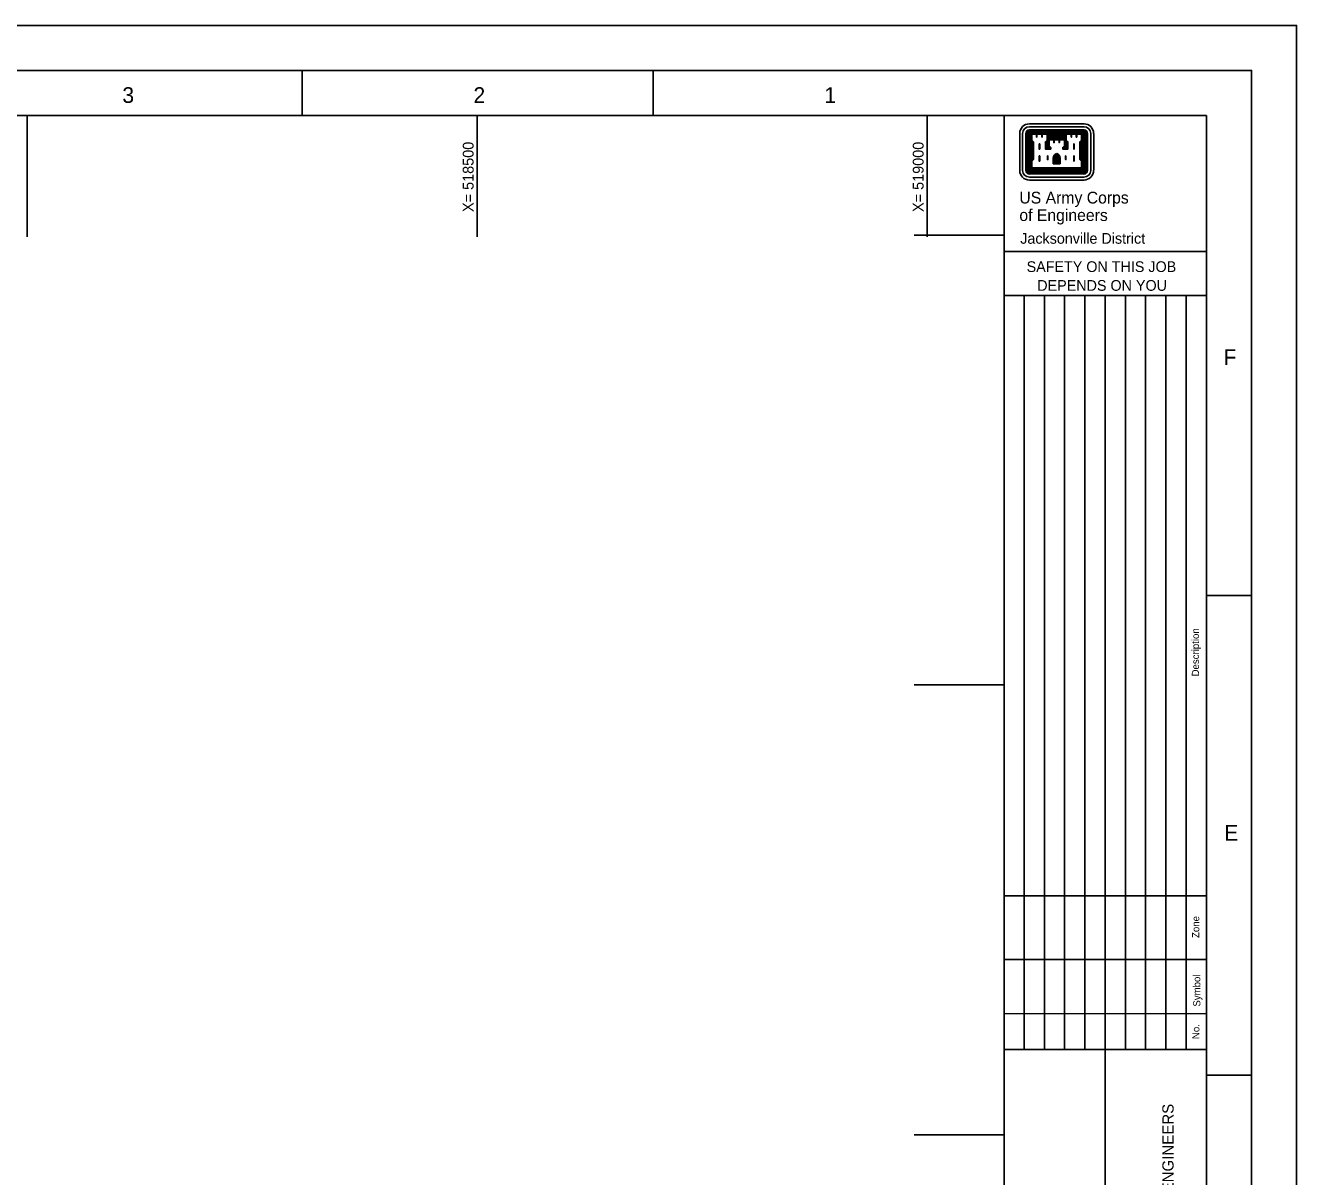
# Model space of a CAD drawing. Extents: x 515010 to 519411, y 1296833 to 1300233.
# Drawn here: x 517998 to 519410, y 1298953 to 1300233 of the extents above; entities that cross this region are included whole.
import ezdxf

# ---------------------------------------------------------------- set-up
doc = ezdxf.new("R2010")
doc.units = 0
for name, color, linetype in [('G-ANNO-NPLT', 7, 'Continuous'), ('G-ANNO-TEXT-LOGO', 7, 'Continuous'), ('G-ANNO-TEXT-TTLB', 7, 'Continuous'), ('G-ANNO-TTLB', 7, 'Continuous'), ('V-TOPO-COOR-STAT', 7, 'Continuous')]:
    doc.layers.add(name, color=color, linetype=linetype)

msp = doc.modelspace()

# ---------------------------------------------------------------- linework, layer by layer
at = {"layer": 'G-ANNO-NPLT'}
msp.add_lwpolyline([(515010.4, 1300233), (519410.4, 1300233), (519410.4, 1296833), (515010.4, 1296833)], close=True, dxfattribs=at)
msp.add_lwpolyline([(519410.4, 1300183), (519410.4, 1300233), (519360.4, 1300233)], dxfattribs=at)
at = {"layer": 'G-ANNO-TEXT-LOGO'}
for p, q in [((519102.8, 1300112.9), (519102.8, 1300071.9)), ((519106, 1300071.9), (519106, 1300112.9)), ((519109.5, 1300112.9), (519109.5, 1300071.9)), ((519110.4, 1300112.9), (519110.4, 1300071.9)), ((519111.2, 1300112.9), (519111.2, 1300071.9)), ((519112.1, 1300112.9), (519112.1, 1300071.9)), ((519113, 1300112.9), (519113, 1300071.9)), ((519174.3, 1300123.6), (519113.5, 1300123.6)), ((519113.5, 1300120.4), (519174.3, 1300120.4)), ((519174.3, 1300117), (519113.5, 1300117)), ((519174.3, 1300116.1), (519113.5, 1300116.1)), ((519174.3, 1300115.2), (519113.5, 1300115.2)), ((519174.3, 1300114.4), (519113.5, 1300114.4)), ((519174.3, 1300113.5), (519113.5, 1300113.5)), ((519113.9, 1300112.9), (519113.9, 1300072.2)), ((519114.7, 1300112.9), (519114.7, 1300073.1)), ((519134.6, 1300112.7), (519153.2, 1300112.7)), ((519134.6, 1300111.8), (519153.2, 1300111.8)), ((519173.1, 1300112.9), (519173.1, 1300073.1)), ((519173.9, 1300112.9), (519173.9, 1300072.2)), ((519174.8, 1300112.9), (519174.8, 1300071.9)), ((519175.7, 1300112.9), (519175.7, 1300071.9)), ((519176.5, 1300112.9), (519176.5, 1300071.9)), ((519177.4, 1300112.9), (519177.4, 1300071.9)), ((519178.3, 1300112.9), (519178.3, 1300071.9)), ((519181.7, 1300112.9), (519181.7, 1300071.9)), ((519185, 1300071.9), (519185, 1300112.9)), ((519115.4, 1300104.2), (519115.4, 1300083.2)), ((519116.3, 1300103.3), (519116.3, 1300084.2)), ((519134.6, 1300111), (519153.2, 1300111)), ((519134.6, 1300110.1), (519153.2, 1300110.1)), ((519134.6, 1300109.2), (519153.2, 1300109.2)), ((519134.6, 1300108.4), (519153.2, 1300108.4)), ((519134.6, 1300107.5), (519153.2, 1300107.5)), ((519171.5, 1300103.3), (519171.5, 1300084.2)), ((519172.4, 1300104.1), (519172.4, 1300083.3)), ((519139.9, 1300079), (519139.9, 1300085.7)), ((519140.7, 1300079), (519140.7, 1300085.7)), ((519141.6, 1300079), (519141.6, 1300085.7)), ((519142.5, 1300079), (519142.5, 1300085.7)), ((519143.3, 1300079), (519143.3, 1300085.7)), ((519144.5, 1300079), (519144.5, 1300085.7)), ((519145.3, 1300079), (519145.3, 1300085.7)), ((519146.2, 1300079), (519146.2, 1300085.7)), ((519147.1, 1300079), (519147.1, 1300085.7)), ((519147.9, 1300079), (519147.9, 1300085.7)), ((519174.3, 1300071.3), (519113.5, 1300071.3)), ((519174.3, 1300070.5), (519113.5, 1300070.5)), ((519174.3, 1300069.6), (519113.5, 1300069.6)), ((519173.9, 1300072.2), (519113.9, 1300072.2)), ((519173.1, 1300073.1), (519114.7, 1300073.1)), ((519139.9, 1300079), (519147.9, 1300079)), ((519174.3, 1300068.7), (519113.5, 1300068.7)), ((519174.3, 1300067.9), (519113.5, 1300067.9)), ((519174.3, 1300064.4), (519113.5, 1300064.4)), ((519113.5, 1300061.1), (519174.3, 1300061.1))]:
    msp.add_line(p, q, dxfattribs=at)
for points in [[(519115.4, 1300112.9), (519115.4, 1300105), (519117.1, 1300103.3), (519117.1, 1300084.2), (519115.4, 1300082.4), (519115.4, 1300073.7), (519172.4, 1300073.7), (519172.4, 1300082.4), (519170.6, 1300084.2), (519170.6, 1300103.3), (519172.4, 1300105), (519172.4, 1300112.9), (519164.9, 1300112.9), (519159.1, 1300112.9), (519153.7, 1300112.9), (519153.7, 1300105), (519155.6, 1300103.3), (519155.6, 1300096.3), (519151.4, 1300096.3), (519151.4, 1300097), (519153.2, 1300098.8), (519153.2, 1300106.6), (519145.7, 1300106.6), (519139.9, 1300106.6), (519134.6, 1300106.6), (519134.6, 1300098.8), (519136.4, 1300097), (519136.4, 1300096.3), (519132.2, 1300096.3), (519132.2, 1300103.3), (519134, 1300105), (519134, 1300112.9), (519126.5, 1300112.9), (519120.7, 1300112.9), (519115.4, 1300112.9)], [(519116.2, 1300112), (519116.2, 1300105.4), (519118, 1300103.6), (519118, 1300083.8), (519116.2, 1300082), (519116.2, 1300074.6), (519171.6, 1300074.6), (519171.6, 1300082), (519169.7, 1300083.8), (519169.7, 1300103.6), (519171.6, 1300105.4), (519171.6, 1300112), (519166.2, 1300112), (519166.2, 1300108.9), (519165.7, 1300108.9), (519165.7, 1300112), (519160.4, 1300112), (519160.4, 1300108.9), (519160, 1300108.9), (519160, 1300112), (519154.6, 1300112), (519154.6, 1300105.4), (519156.4, 1300103.6), (519156.4, 1300095.5), (519150.6, 1300095.5), (519150.6, 1300097.4), (519152.4, 1300099.2), (519152.4, 1300105.8), (519147, 1300105.8), (519147, 1300102.7), (519146.6, 1300102.7), (519146.6, 1300105.8), (519141.2, 1300105.8), (519141.2, 1300102.7), (519140.7, 1300102.7), (519140.7, 1300105.8), (519135.4, 1300105.8), (519135.4, 1300099.2), (519137.2, 1300097.4), (519137.2, 1300095.5), (519131.4, 1300095.5), (519131.4, 1300103.6), (519133.2, 1300105.4), (519133.2, 1300112), (519127.9, 1300112), (519127.9, 1300108.9), (519127.4, 1300108.9), (519127.4, 1300112), (519122, 1300112), (519122, 1300108.9), (519121.6, 1300108.9), (519121.6, 1300112), (519116.2, 1300112)], [(519124.4, 1300101.3), (519124.4, 1300095.5), (519125, 1300095.5), (519125, 1300101.3), (519124.4, 1300101.3)], [(519133.6, 1300103.4), (519133.1, 1300102.9), (519133.1, 1300097.2), (519135, 1300097.2), (519133.7, 1300098.5), (519133.7, 1300103.5)], [(519154.2, 1300103.4), (519154.7, 1300102.9), (519154.7, 1300097.2), (519152.9, 1300097.2), (519154.1, 1300098.5), (519154.1, 1300103.5)], [(519163.3, 1300101.3), (519163.3, 1300095.5), (519162.8, 1300095.5), (519162.8, 1300101.3), (519163.3, 1300101.3)], [(519124.4, 1300088), (519124.4, 1300082.1), (519125, 1300082.1), (519125, 1300088), (519124.4, 1300088)], [(519133.6, 1300088), (519133.6, 1300083.9), (519134.1, 1300083.9), (519134.1, 1300088), (519133.6, 1300088)], [(519154.2, 1300088), (519154.2, 1300083.9), (519153.7, 1300083.9), (519153.7, 1300088), (519154.2, 1300088)], [(519163.3, 1300088), (519163.3, 1300082.1), (519162.8, 1300082.1), (519162.8, 1300088), (519163.3, 1300088)]]:
    msp.add_lwpolyline(points, dxfattribs=at)
for centre, major_axis, start_param, end_param in [((519113.5, 1300112.9), (10.7, 0), 1.57078, 3.141576), ((519113.5, 1300112.9), (7.49, 0), 1.57078, 3.141576), ((519113.5, 1300112.9), (4.02, 0), 1.57078, 3.141576), ((519113.5, 1300112.9), (3.15, 0), 1.57078, 3.141576), ((519113.5, 1300112.9), (2.28, 0), 1.57078, 3.141576), ((519113.5, 1300112.9), (1.41, 0), 1.57078, 3.141576), ((519113.5, 1300112.9), (0.546, 0), 1.57078, 3.141576), ((519174.2, 1300112.9), (10.7, 0), 6.283169, 7.853965), ((519174.2, 1300112.9), (7.49, 0), 6.28317, 7.853966), ((519174.2, 1300112.9), (4.02, 0), 6.283169, 7.853965), ((519174.2, 1300112.9), (3.15, 0), 6.283169, 7.853965), ((519174.2, 1300112.9), (2.28, 0), 6.283169, 7.853965), ((519174.2, 1300112.9), (1.41, 0), 6.283169, 7.853965), ((519174.2, 1300112.9), (0.546, 0), 6.283169, 7.853965), ((519145.4, 1300085.2), (-5.55, 0), 4.985832, 6.214359), ((519145.4, 1300085.2), (-4.69, 0), 4.947465, 6.21436), ((519145.4, 1300085.2), (-3.82, 0), 4.947465, 6.21436), ((519145.4, 1300085.2), (-2.95, 0), 4.947465, 6.21436), ((519142.4, 1300085.2), (2.08, 0), 0.068794, 1.335689), ((519142.4, 1300085.2), (2.95, 0), 0.068794, 1.335689), ((519142.4, 1300085.2), (3.82, 0), 0.068795, 1.335689), ((519145.4, 1300085.2), (-2.08, 0), 4.947465, 6.214359), ((519142.4, 1300085.2), (4.69, 0), 0.068795, 1.335689), ((519142.4, 1300085.2), (5.55, 0), 0.068795, 1.29842), ((519113.5, 1300071.8), (-10.7, 0), 6.28317, 7.853966), ((519113.5, 1300071.8), (-7.49, 0), 6.28317, 7.853966), ((519113.5, 1300071.8), (-4.02, 0), 6.28317, 7.853966), ((519113.5, 1300071.8), (-3.15, 0), 6.28317, 7.853966), ((519113.5, 1300071.8), (-2.28, 0), 6.28317, 7.853966), ((519113.5, 1300071.8), (-1.41, 0), 6.28317, 7.853966), ((519113.5, 1300071.8), (-0.546, 0), 6.28317, 7.853966), ((519174.2, 1300071.8), (4.02, 0), 4.712373, 6.28317), ((519174.2, 1300071.8), (3.15, 0), 4.712373, 6.28317), ((519174.2, 1300071.8), (2.28, 0), 4.712373, 6.28317), ((519174.2, 1300071.8), (1.41, 0), 4.712373, 6.28317), ((519174.2, 1300071.8), (0.546, 0), 4.712373, 6.28317), ((519174.2, 1300071.8), (10.7, 0), 4.712373, 6.28317), ((519174.2, 1300071.8), (-7.49, 0), 1.570781, 3.141577)]:
    msp.add_ellipse(centre, major_axis=major_axis, ratio=0.99964, start_param=start_param, end_param=end_param, dxfattribs=at)
at = {"layer": 'G-ANNO-TTLB'}
for p, q in [((518305.4, 1300183), (518305.4, 1300133)), ((518695.4, 1300183), (518695.4, 1300133)), ((519085.4, 1300133), (519085.4, 1296933)), ((519085.4, 1299981.7), (519310.4, 1299981.7)), ((519084.8, 1299932.6), (519309.8, 1299932.6)), ((519107.7, 1299932.6), (519107.7, 1299094.7)), ((519130.2, 1299932.6), (519130.2, 1299094.7)), ((519152.7, 1299932.6), (519152.7, 1299094.7)), ((519175.2, 1299932.6), (519175.2, 1299094.7)), ((519197.7, 1299932.6), (519197.7, 1299094.7)), ((519220.2, 1299932.6), (519220.2, 1299094.7)), ((519242.7, 1299932.6), (519242.7, 1299094.7)), ((519265.2, 1299932.6), (519265.2, 1299094.7)), ((519287.7, 1299932.6), (519287.7, 1299094.7)), ((519360.4, 1299599.5), (519310.4, 1299599.5)), ((519085.4, 1299265.7), (519310.4, 1299265.7)), ((519085.4, 1299194.6), (519310.4, 1299194.6)), ((519085.4, 1299134.6), (519310.4, 1299134.5)), ((519085.4, 1299094.7), (519310.4, 1299094.7)), ((519197.3, 1298235.1), (519197.9, 1299094.7)), ((519197.9, 1299094.7), (519197.9, 1299059.3)), ((519360.4, 1299066.2), (519310.4, 1299066.2))]:
    msp.add_line(p, q, dxfattribs=at)
for points in [[(515060.4, 1296883), (519360.4, 1296883), (519360.4, 1300183), (515060.4, 1300183)], [(519310.4, 1300133), (515185.4, 1300133), (515185.4, 1296933), (519310.4, 1296933)]]:
    msp.add_lwpolyline(points, close=True, dxfattribs=at)
at = {"layer": 'V-TOPO-COOR-STAT'}
for p, q in [((518000, 1299998), (518000, 1300133)), ((518500, 1299998), (518500, 1300133)), ((519000, 1299998), (519000, 1300133)), ((519085.4, 1300000), (518985.4, 1300000)), ((519085.4, 1299500), (518985.4, 1299500)), ((519085.4, 1299000), (518985.4, 1299000))]:
    msp.add_line(p, q, dxfattribs=at)

# ---------------------------------------------------------------- texts
at = {"layer": 'G-ANNO-TEXT-TTLB'}
for s, height, p in [('US Army Corps', 13.086, (519102.4, 1300035)), ('of Engineers', 13.086, (519102.4, 1300015.6)), ('Jacksonville District', 11.9, (519103.4, 1299990.3)), ('SAFETY ON THIS JOB', 11.9, (519110.5, 1299958.9)), ('DEPENDS ON YOU', 11.9, (519122.3, 1299938))]:
    msp.add_text(s, height=height, dxfattribs=at).set_placement(p)
for s, height, p in [('Description', 8, (519302, 1299509.4)), ('Zone', 8, (519302.3, 1299218.7)), ('Symbol', 8, (519303.5, 1299142.4)), ('No.', 8, (519302.5, 1299106.3)), ('JACKSONVILLE DISTRICT, CORPS OF ENGINEERS', 12.5, (519273.8, 1298628.5))]:
    msp.add_text(s, height=height, rotation=90, dxfattribs=at).set_placement(p)
at = {"layer": 'G-ANNO-TTLB'}
for s, p in [('3', (518105.8, 1300146.8)), ('2', (518495.9, 1300146.8)), ('1', (518885.8, 1300146.8)), ('F', (519329.2, 1299855.6)), ('E', (519330, 1299326.8))]:
    msp.add_text(s, height=17.5, dxfattribs=at).set_placement(p)
at = {"layer": 'V-TOPO-COOR-STAT'}
for s, p in [('X= 518500', (518496, 1300025.6)), ('X= 519000', (518996, 1300025.6))]:
    msp.add_text(s, height=12, rotation=90, dxfattribs=at).set_placement(p)

doc.saveas('drawing.dxf')
